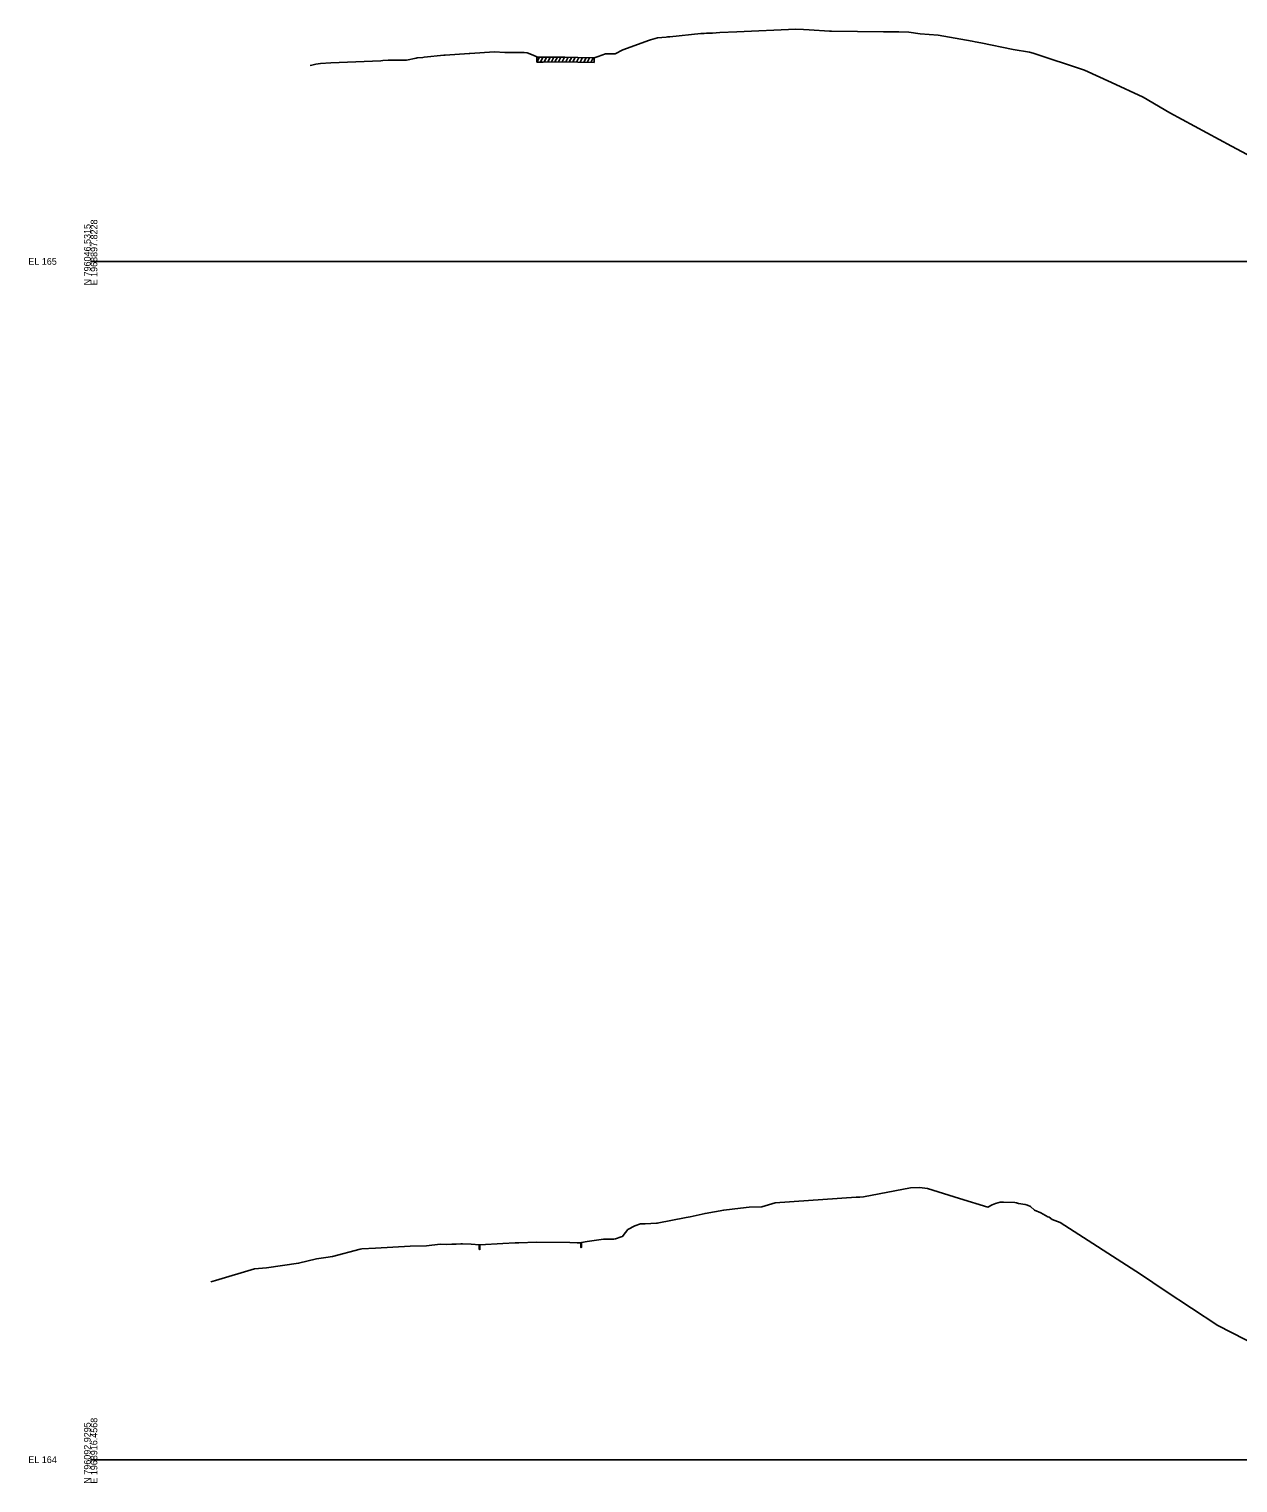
# Model space of a CAD drawing. Extents: x 1017 to 19997, y -1947 to 50737.
# Drawn here: x 15974 to 16479, y 3990 to 4597 of the extents above; entities that cross this region are included whole.
import ezdxf

# ---------------------------------------------------------------- set-up
doc = ezdxf.new("R2010")
doc.units = 0
for name, color, linetype in [('RD_GPK_XS_Cell', 7, 'Continuous'), ('RD_XS_ExGround', 7, 'Continuous'), ('RD_XS_ExPaveRet', 7, 'Continuous')]:
    doc.layers.add(name, color=color, linetype=linetype)

msp = doc.modelspace()

# ---------------------------------------------------------------- linework, layer by layer
at = {"layer": 'RD_GPK_XS_Cell'}
for p, q in [((16000, 4500), (16600, 4500)), ((16000, 4000), (16600, 4000))]:
    msp.add_line(p, q, dxfattribs=at)
at = {"layer": 'RD_XS_ExGround'}
for points in [[(16091.61, 4581.77), (16092.27, 4581.92), (16093.97, 4582.34), (16095.88, 4582.61), (16100.16, 4582.82), (16121.13, 4583.73), (16121.93, 4583.85), (16124.18, 4583.91), (16127.54, 4583.94), (16131.76, 4583.99), (16135.79, 4584.82), (16136.22, 4584.89), (16138.6, 4585.12), (16139.11, 4585.17), (16147.31, 4585.99), (16147.89, 4586.06), (16157.92, 4586.78), (16158.24, 4586.78), (16168.45, 4587.4), (16172.85, 4587.18), (16173.45, 4587.12), (16174.05, 4587.12), (16177.25, 4587.11), (16177.81, 4587.12), (16180.86, 4587.12), (16182.08, 4587.03), (16184.6, 4586.03), (16186.13, 4585.36), (16186.23, 4585.16), (16188.88, 4585.17), (16197.83, 4585.27), (16203.27, 4585.12), (16210.13, 4584.93), (16211.72, 4585.45), (16213.26, 4586.02), (16214.84, 4586.6), (16217.59, 4586.67), (16218.82, 4586.67), (16222.04, 4588.32), (16233.14, 4592.29), (16233.58, 4592.4), (16236.55, 4593.24), (16240.12, 4593.59), (16240.73, 4593.68), (16241.08, 4593.74), (16241.67, 4593.77), (16254.64, 4595.07), (16256.06, 4595.13), (16256.98, 4595.18), (16259.46, 4595.29), (16262.47, 4595.45), (16269.59, 4595.78), (16294.21, 4596.94), (16297.5, 4596.75), (16299.87, 4596.61), (16308.27, 4596.1), (16309.11, 4596.09), (16330.84, 4595.81), (16337.18, 4595.72), (16341.44, 4595.7), (16346.15, 4594.95), (16353.57, 4594.46), (16367.88, 4591.84), (16369.06, 4591.65), (16371.39, 4591.24), (16384.99, 4588.45), (16391.7, 4587.34), (16393.33, 4586.86), (16414.7, 4579.73), (16425.95, 4574.67), (16439.24, 4568.59), (16450.26, 4561.93), (16476.08, 4548.09), (16482.58, 4544.64)], [(16050.11, 4074.27), (16052.12, 4074.8), (16068.36, 4079.58), (16073.41, 4080.12), (16086.78, 4081.94), (16094.23, 4083.77), (16098.18, 4084.33), (16100.85, 4084.76), (16112.51, 4087.89), (16113.2, 4087.92), (16118.83, 4088.24), (16133.37, 4089.03), (16140.07, 4089.2), (16145.82, 4089.9), (16148.65, 4089.85), (16150.65, 4089.91), (16152.49, 4089.99), (16154.44, 4090.06), (16155.15, 4090.07), (16158.77, 4089.91), (16162.32, 4089.7), (16162.45, 4089.59), (16172, 4090.17), (16177.08, 4090.42), (16178.62, 4090.48), (16186.1, 4090.75), (16199.91, 4090.63), (16203.03, 4090.55), (16204.7, 4090.47), (16204.82, 4090.67), (16207.19, 4091.02), (16214.03, 4092.06), (16217.97, 4092.06), (16218.3, 4092.06), (16219.05, 4092.18), (16221.41, 4092.97), (16221.93, 4093.13), (16222.25, 4093.56), (16224.11, 4096.01), (16227.07, 4097.52), (16229.43, 4098.39), (16231.41, 4098.43), (16236.05, 4098.63), (16236.39, 4098.68), (16248.55, 4101.08), (16250.12, 4101.37), (16256.38, 4102.79), (16264.15, 4104.12), (16271.21, 4104.93), (16274.72, 4105.43), (16280.06, 4105.54), (16285.66, 4107.14), (16319.47, 4109.48), (16320.96, 4109.53), (16322.45, 4109.74), (16342.14, 4113.48), (16345.81, 4113.58), (16349.17, 4113.12), (16362.6, 4108.97), (16374.39, 4105.31), (16376.17, 4106.38), (16377.52, 4106.96), (16379.44, 4107.45), (16380.11, 4107.46), (16380.84, 4107.44), (16385.62, 4107.3), (16386.37, 4107.13), (16387.11, 4106.86), (16389.89, 4106.49), (16390.88, 4106.17), (16392.1, 4105.59), (16393.84, 4104.15), (16396.5, 4103.01), (16399.35, 4101.4), (16399.97, 4101.19), (16401.22, 4100.25), (16404.5, 4098.96), (16438, 4077.38), (16448.3, 4070.44), (16470.33, 4056.06), (16493.37, 4044.23)]]:
    msp.add_lwpolyline(points, dxfattribs=at)
at = {"layer": 'RD_XS_ExPaveRet'}
for p, q in [((16186.23, 4583.16), (16187.24, 4585.16)), ((16186.23, 4583.16), (16186.23, 4585.16)), ((16186.23, 4583.16), (16188.88, 4583.17)), ((16187.73, 4583.17), (16188.74, 4585.17)), ((16188.88, 4583.17), (16197.83, 4583.27)), ((16189.23, 4583.18), (16190.24, 4585.19)), ((16190.73, 4583.19), (16191.74, 4585.2)), ((16192.23, 4583.21), (16193.24, 4585.22)), ((16193.73, 4583.22), (16194.74, 4585.23)), ((16195.23, 4583.24), (16196.24, 4585.25)), ((16196.73, 4583.26), (16197.74, 4585.27)), ((16197.83, 4583.27), (16203.27, 4583.12)), ((16198.23, 4583.26), (16199.22, 4585.23)), ((16199.73, 4583.22), (16200.72, 4585.19)), ((16201.23, 4583.18), (16202.22, 4585.15)), ((16202.73, 4583.13), (16203.72, 4585.11)), ((16203.27, 4583.12), (16210.13, 4582.93)), ((16204.23, 4583.09), (16205.22, 4585.07)), ((16205.73, 4583.05), (16206.72, 4585.02)), ((16207.23, 4583.01), (16208.22, 4584.98)), ((16208.73, 4582.97), (16209.72, 4584.94)), ((16210.13, 4584.93), (16210.13, 4582.93)), ((16162.17, 4087.71), (16162.17, 4089.71)), ((16162.45, 4089.59), (16162.45, 4087.59)), ((16204.54, 4088.48), (16204.54, 4090.48)), ((16204.82, 4090.67), (16204.82, 4088.67)), ((16162.17, 4087.71), (16162.32, 4087.7)), ((16162.32, 4087.7), (16162.45, 4087.59)), ((16204.54, 4088.48), (16204.7, 4088.47)), ((16204.7, 4088.47), (16204.82, 4088.67))]:
    msp.add_line(p, q, dxfattribs=at)

# ---------------------------------------------------------------- texts
at = {"layer": 'RD_GPK_XS_Cell'}
for s, p in [('N 796046.5315', (16000, 4490)), ('E 1968897.8228', (16002.8, 4490)), ('E 1968916.4568', (16002.8, 3990)), ('N 796092.9295', (16000, 3990))]:
    msp.add_text(s, height=2.8, rotation=90, dxfattribs=at).set_placement(p)
for s, p in [('EL 165', (15974, 4498.6)), ('EL 164', (15974, 3998.6))]:
    msp.add_text(s, height=2.8, dxfattribs=at).set_placement(p)

doc.saveas('drawing.dxf')
